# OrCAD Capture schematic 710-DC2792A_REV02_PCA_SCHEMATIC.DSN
size Custom; note: DUAL MASTER isoSPI ADAPTER
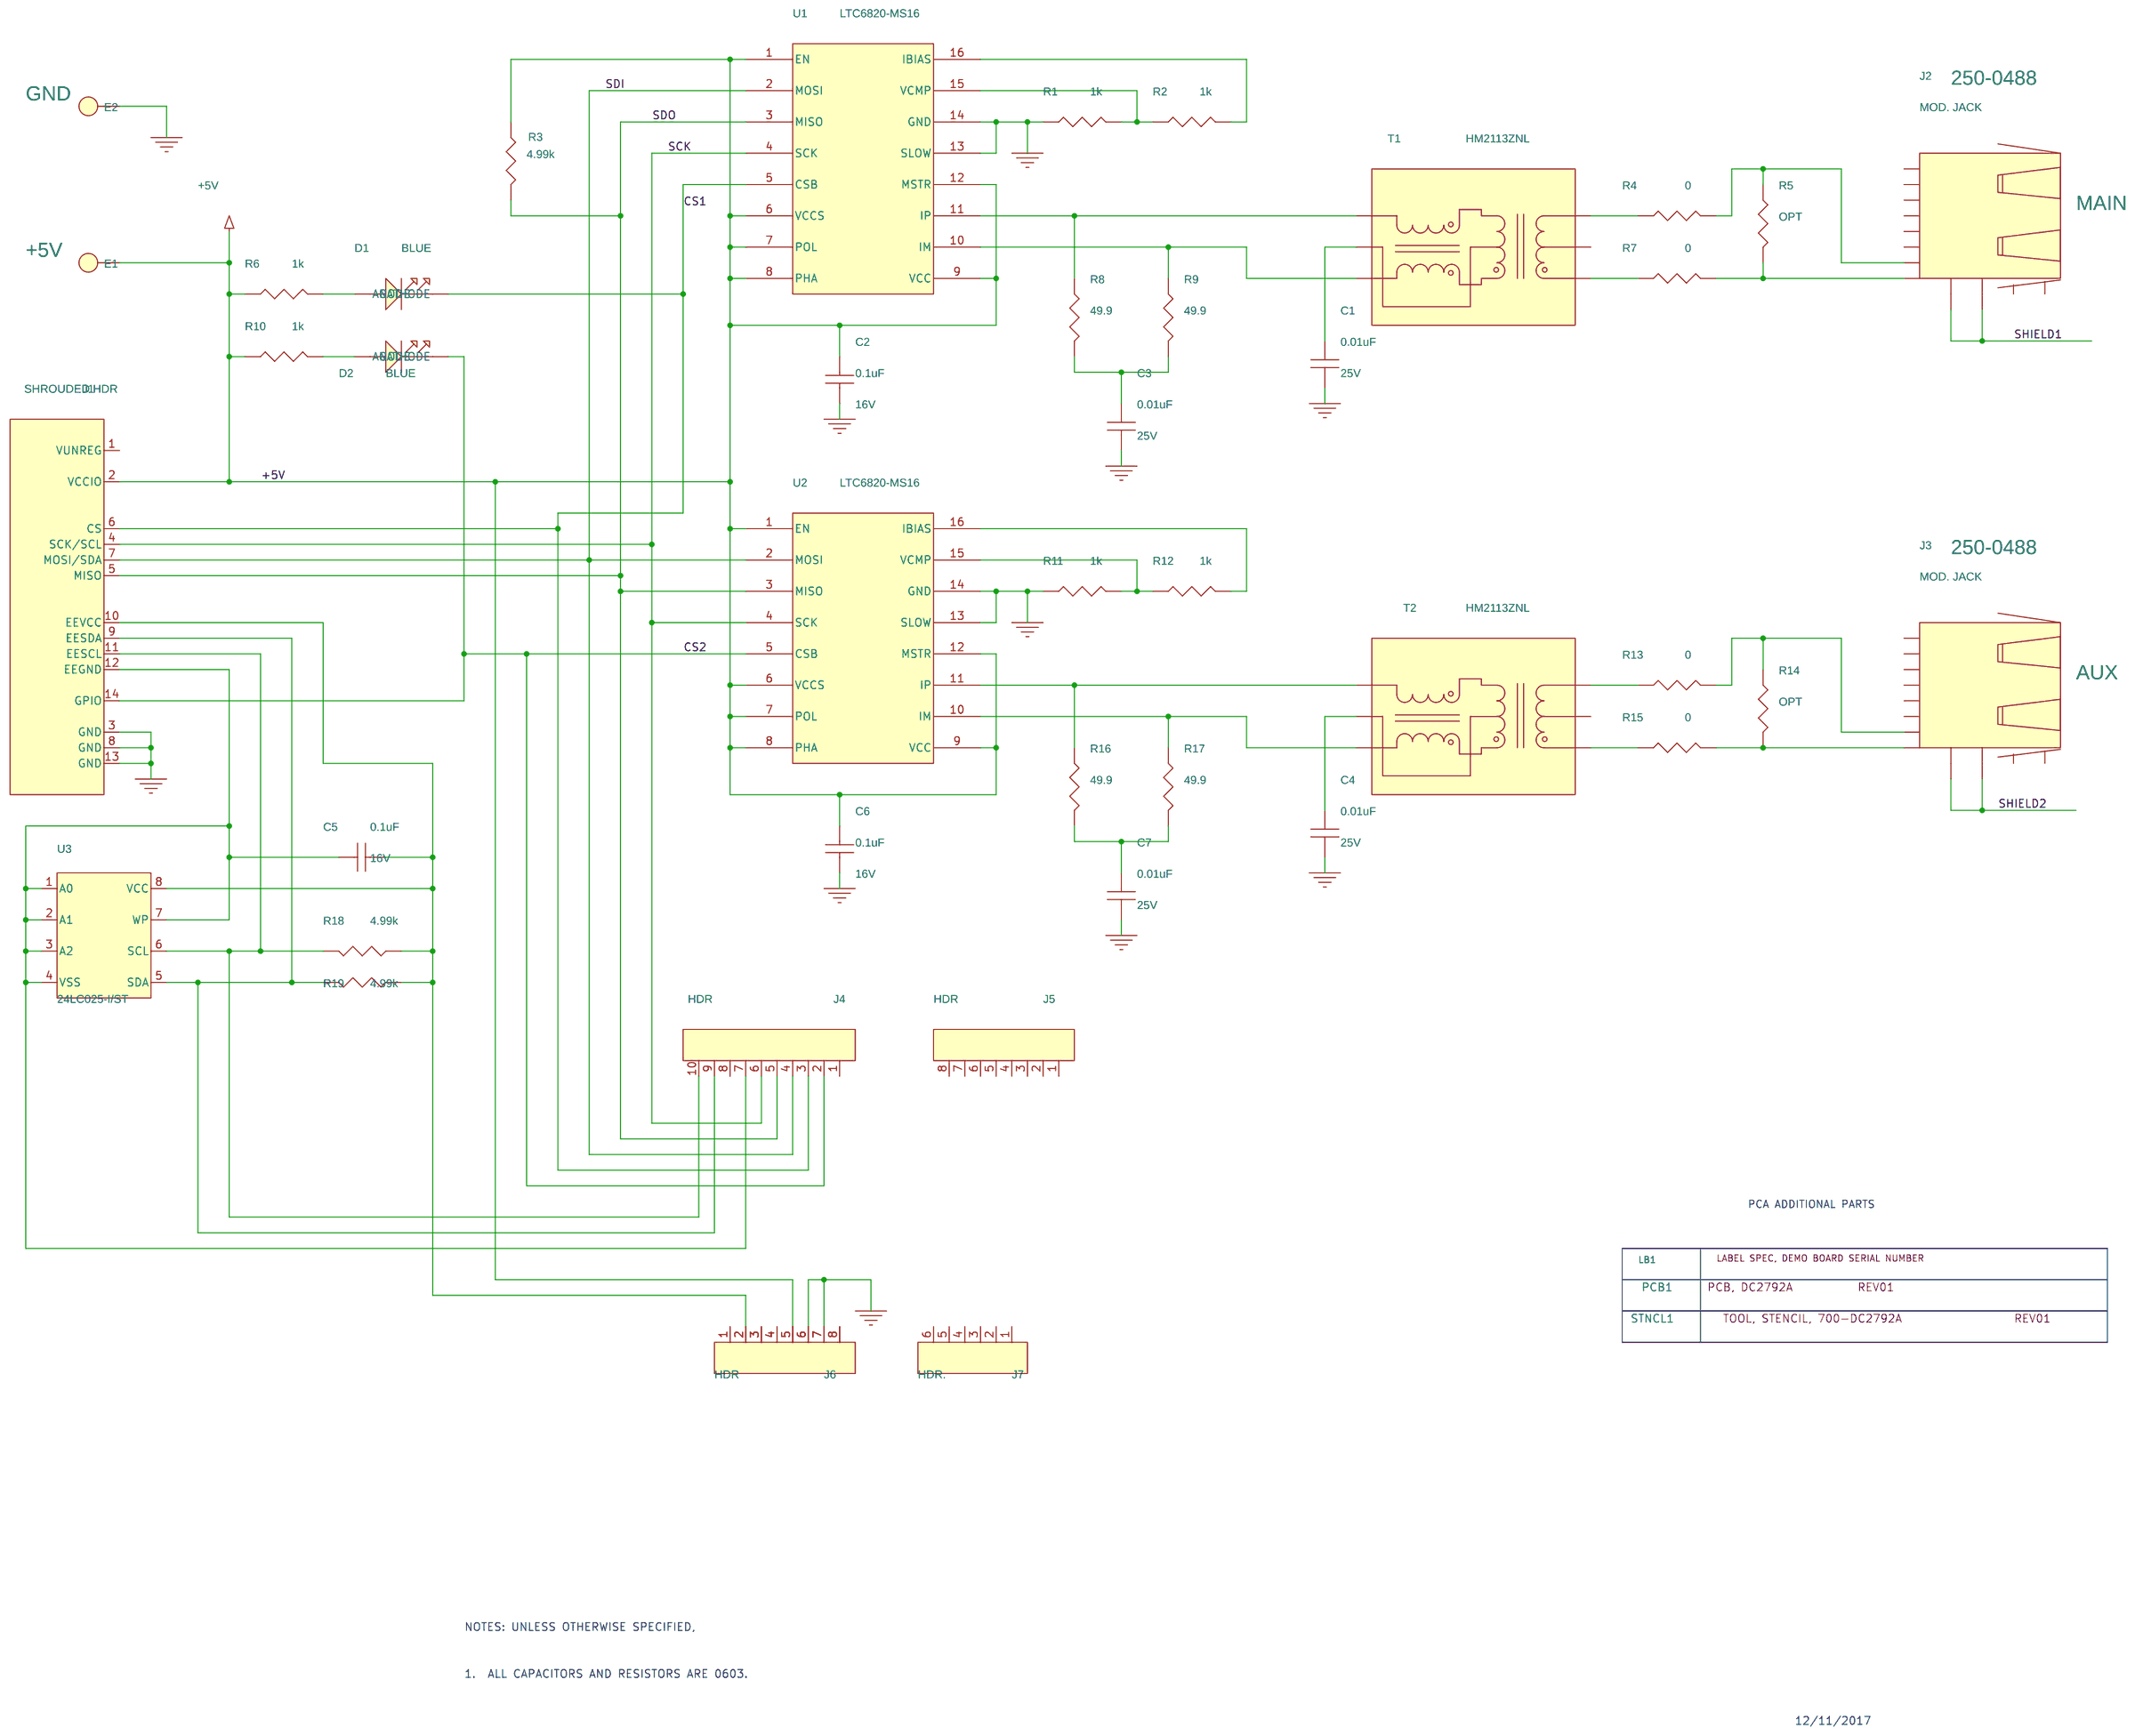
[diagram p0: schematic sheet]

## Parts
C1  0.01uF  [CC0603N]
C2  0.1uF  [CC0603N]
C3  0.01uF  [CC0603N]
C4  0.01uF  [CC0603N]
C5  0.1uF  [CC0603N]
C6  0.1uF  [CC0603N]
C7  0.01uF  [CC0603N]
D1  BLUE  [LED_0603]
D2  BLUE  [LED_0603]
E1  TEST POINT  [MILLMAX2308]
E2  TEST POINT  [MILLMAX2308]
J1  SHROUDED HDR  [HD2X7-079-MOLEX]
J2  MOD. JACK  [CON-RJ45-5406298]
J3  MOD. JACK  [CON-RJ45-5406298]
J4  HDR  [HD1X10-100]
J5  HDR  [HD1X8-100]
J6  HDR  [HD1X8-100]
J7  HDR.  [HD1X6-100]
LB1  LABEL  [895-0154_REV01]
PCB1  PCB, DC2792A
R1  1k  [CR0603N]
R2  1k  [CR0603N]
R3  4.99k  [CR0603N]
R4  0  [CR0603N]
R5  OPT  [CR0603N]
R6  1k  [CR0603N]
R7  0  [CR0603N]
R8  49.9  [CR0603N]
R9  49.9  [CR0603N]
R10  1k  [CR0603N]
R11  1k  [CR0603N]
R12  1k  [CR0603N]
R13  0  [CR0603N]
R14  OPT  [CR0603N]
R15  0  [CR0603N]
R16  49.9  [CR0603N]
R17  49.9  [CR0603N]
R18  4.99k  [CR0603N]
R19  4.99k  [CR0603N]
STNCL1  TOOL, STENCIL, DC2792A
T1  HM2113ZNL  [PULSE-HM2113ZNL]
T2  HM2113ZNL  [PULSE-HM2113ZNL]
U1  LTC6820-MS16  [LTC-MS-16-1669]
U2  LTC6820-MS16  [LTC-MS-16-1669]
U3  24LC025-I/ST  [MICROCHIP-TSSOP-8]

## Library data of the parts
C1 C3 C4 C7 = CAP: CAP.,0.01uF,X7R,25V,10%,0603; CLASS: DISCRETE; Dielectric Type: X7R; FPLIST: CC0603N,CC0603L,CC0603M; Inventory Qty: 19588; Manufacturer: AVX; Manufacturer PN: 06033C103KAT2A; PART_NUMBER: 150-3225; Package Size: 0603; Rated Voltage: 25V; Tolerance: 10%; UserField01: AEC-Q200, NO SUBS ALLOWED
C2 C5 C6 = CAP: CAP.,0.1uF,X7R,16V,10%,0603,AEC-Q200; CLASS: DISCRETE; Dielectric Type: X7R; FPLIST: CC0603N,CC0603L,CC0603M; Inventory Qty: 12770; Manufacturer: KEMET; Manufacturer PN: C0603C104K4RACAUTO; PART_NUMBER: 150-3311; Package Size: 0603; Rated Voltage: 16V; Tolerance: 10%; UserField01: AEC-Q200
D1 D2 = LED: LED,BLUE,WATER CLEAR,0603; CLASS: DISCRETE; Inventory Qty: 12068; Manufacturer: LUMEX; Manufacturer PN: SML-LXFP0603USBCTR; PART_NUMBER: 270-0119; Package Size: 0603 (1608 Metric); Package Type: 0603
E1 = TEST_POINT_.156_MILL-MAX_2308: TEST POINT,TURRET,0.064" MTG. HOLE,PCB 0.062" THICK; 1: +5V; BOM NOTES: NO STUFF; CLASS: IO; Inventory Qty: 835987; Manufacturer: MILL-MAX; Manufacturer PN: 2308-2-00-80-00-00-07-0; PART_NUMBER: 260-0004
E2 = TEST_POINT_.156_MILL-MAX_2308: TEST POINT,TURRET,0.064" MTG. HOLE,PCB 0.062" THICK; 1: GND; BOM NOTES: NO STUFF; CLASS: IO; Inventory Qty: 835987; Manufacturer: MILL-MAX; Manufacturer PN: 2308-2-00-80-00-00-07-0; PART_NUMBER: 260-0004
J1 = CONN_2X7_.079_MOLEX_RIBBON_A: CONN.,SHROUDED HDR,MALE,2x7,2mm,VERT,STR,THT; CLASS: IO; Inventory Qty: 26574; Manufacturer: MOLEX; Manufacturer PN: 87831-1420; PART_NUMBER: 250-0403
J2 = JACK_RJ45_SHIELDED: CONN.,MOD. JACK,FEMALE,8POS, 1PORT,R/A THT,SHIELDED; 1: MAIN; CLASS: IO; Inventory Qty: 9320; Manufacturer: TE CONNECTIVITY; Manufacturer PN: 5406298-1; PART_NUMBER: 250-0488
J3 = JACK_RJ45_SHIELDED: CONN.,MOD. JACK,FEMALE,8POS, 1PORT,R/A THT,SHIELDED; 1: AUX; CLASS: IO; Inventory Qty: 9320; Manufacturer: TE CONNECTIVITY; Manufacturer PN: 5406298-1; PART_NUMBER: 250-0488
J4 = CON10_0: CONN.,HDR,MALE,1x10,2.54mm,VERT, STR, THT; CLASS: IO; Inventory Qty: 11032; Manufacturer: SAMTEC; Manufacturer PN: TSW-110-07-L-S; PART_NUMBER: 250-0606
J5 J6 = CON8: CONN.,HDR,MALE,1x8,2.54mm,VERT, STR, THT; CLASS: IO; Inventory Qty: 4158; Manufacturer: SAMTEC; Manufacturer PN: TSW-108-07-L-S; PART_NUMBER: 250-0573
J7 = CON6: CONN.,HDR.,MALE,1x6,2.54mm,THT, STR; CLASS: IO; Inventory Qty: 12302; Manufacturer: SAMTEC; Manufacturer PN: TSW-106-07-L-S; PART_NUMBER: 250-0537
LB1 = BLANK_LABEL: LABEL SPEC, DEMO BOARD SERIAL NUMBER; Inventory Qty: 0; Manufacturer: BRADY; Manufacturer PN: THT-96-717-10; PART_NUMBER: 895-0154
PCB1 = BLANK_PCB_PART: BOM Notes: REV01; CLASS: DISCRETE; Inventory Qty: 0; Manufacturer: EAGLE TECH. INC.; Manufacturer PN: 600-DC2792A; PART_NUMBER: 600-DC2792A
R1 R2 R6 R10-R12 = RES: RES.,1k OHMS,5%,1/10W,0603; CLASS: DISCRETE; FPLIST: CR0603N,CR0603L,CR0603M; Inventory Qty: 35510; Manufacturer: SAMSUNG; Manufacturer PN: RC1608J102CS; PART_NUMBER: 100-0020; Package Size: 0603; Rated Power: 1/10W; Temperature Coefficient: 100ppm/C; Tolerance: 5%
R3 R18 R19 = RES: RES.,4.99k OHMS,1%,1/10W,0603; CLASS: DISCRETE; FPLIST: CR0603N,CR0603L,CR0603M; Inventory Qty: 62059; Manufacturer: PANASONIC; Manufacturer PN: ERJ3EKF4991V; PART_NUMBER: 100-0121; Package Size: 0603; Rated Power: 1/10W; Temperature Coefficient: 100ppm/C; Tolerance: 1%
R4 R7 R13 R15 = RES: RES.,0 OHM,1/10W,0603,AEC-Q200; CLASS: DISCRETE; FPLIST: CR0603N,CR0603L,CR0603M; Inventory Qty: 627023; Manufacturer: VISHAY; Manufacturer PN: CRCW06030000Z0EA; PART_NUMBER: 100-0009; Package Size: 0603; Rated Power: 1/10W
R5 R14 = RES: RES., OPTION, 0603; CLASS: DISCRETE; FPLIST: CR0603N,CR0603L,CR0603M; PART_NUMBER: 100-2374; Package Size: 0603
R8 R9 R16 R17 = RES: RES.,49.9 OHMS,1%,1/10W,0603; CLASS: DISCRETE; FPLIST: CR0603N,CR0603L,CR0603M; Inventory Qty: 58114; Manufacturer: PANASONIC; Manufacturer PN: ERJ3EKF49R9V; PART_NUMBER: 100-0115; Package Size: 0603; Rated Power: 1/10W; Temperature Coefficient: +/-100ppm; Tolerance: 1%
STNCL1 = BLANK_STENCIL_PART: TOOL, STENCIL, 700-DC2792A; BOM Notes: REV01; CLASS: DISCRETE; Inventory Qty: 0; Manufacturer: LINEAR TECH.; Manufacturer PN: 830-DC2792A; PART_NUMBER: 830-DC2792A
T1 T2 = PULSE-HM2113ZNL: TRANSFORMER,CMC,SGL,1:1 +/-2%,4.3kV,6-pin SMT,AEC-Q200; CLASS: DISCRETE; Inventory Qty: 68; Manufacturer: PULSE; PART_NUMBER: 410-0100; Turns Ratio: 1:1 +/-2%
U1 U2 = LTC6820-MS-ALT1: IC,isoSPI Isolated Comm.Interface,16-pin MSOP; CLASS: IC; Inventory Qty: 69; Manufacturer: LINEAR TECH.; Manufacturer PN: LTC6820IMS#PBF; PART_NUMBER: LTC6820IMS#PBF; Package Size: MS16; Package Type: 16-pin MSOP; Supply Voltage: 2.7V-5.5 V
U3 = 24LC025-I_ST_TSSOP-8: IC, MEMORY,EEPROM,2Kb (256x8),TSSOP-8,400kHz; CLASS: IC; Inventory Qty: 11792; Manufacturer: Microchip; PART_NUMBER: 380-0087; Package Size: TSSOP-8; Package Type: TSSOP-8

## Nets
+5V: C2.1 C6.1 E1.1(A) J1.2(VCCIO) J6.5 R3.1 R6.1 R10.1 U1.1(EN) U1.6(VCCS) U1.7(POL) U1.8(PHA) U1.9(VCC) U1.12(MSTR) U2.1(EN) U2.6(VCCS) U2.7(POL) U2.8(PHA) U2.9(VCC) U2.12(MSTR)
GND: C1.2 C2.2 C3.2 C4.2 C6.2 C7.2 E2.1(A) J1.3(GND) J1.8(GND) J1.13(GND) J6.6 J6.7 R1.1 R11.1 U1.13(SLOW) U1.14(GND) U2.13(SLOW) U2.14(GND)
CS1: D1.1(CATHODE) J1.6(CS) J4.3 U1.5(CSB)
CS2: D2.1(CATHODE) J1.14(GPIO) J4.2 U2.5(CSB)
SCK: J1.4(SCK/SCL) J4.6 U1.4(SCK) U2.4(SCK)
SDI: J1.7(MOSI/SDA) J4.4 U1.2(MOSI) U2.2(MOSI)
SDO: J1.5(MISO) J4.5 R3.2 U1.3(MISO) U2.3(MISO)
SHIELD1: J2.S1 J2.S2
SHIELD2: J3.S1 J3.S2
N27407114: C5.1 J1.12(EEGND) J4.7 U3.1(A0) U3.2(A1) U3.3(A2) U3.4(VSS) U3.7(WP)
N27407193: J1.11(EESCL) J4.10 R18.1 U3.6(SCL)
N27407213: J1.9(EESDA) J4.9 R19.1 U3.5(SDA)
N27407390: C5.2 J1.10(EEVCC) J6.2 R18.2 R19.2 U3.8(VCC)
N27408489: R1.2 R2.1 U1.15(VCMP)
N27408492: R2.2 U1.16(IBIAS)
N27408890: R8.1 T1.4 U1.11(IP)
N27408904: R9.1 T1.6 U1.10(IM)
N27408920: C1.1 T1.5
N27409119: C3.1 R8.2 R9.2
N27409499: J2.2 R4.2 R5.1
N27409511: J2.1 R5.2 R7.2
N27409863: R11.2 R12.1 U2.15(VCMP)
N27409865: R12.2 U2.16(IBIAS)
N27409893: R16.1 T2.4 U2.11(IP)
N27409895: R17.1 T2.6 U2.10(IM)
N27409901: C4.1 T2.5
N27409942: C7.1 R16.2 R17.2
N27409983: J3.2 R13.2 R14.1
N27409997: J3.1 R14.2 R15.2
N27411834: D1.2(ANODE) R6.2
N27411837: D2.2(ANODE) R10.2
N27422700: R7.1 T1.1
N27422702: R4.1 T1.3
N27422768: R15.1 T2.1
N27422770: R13.1 T2.3

Not connected (* = marked no-connect by the designer): J1 1(VUNREG); J2 3 4 5 6 7 8; J3 3 4 5 6 7 8; J4 1 8; J5 1 2 3 4 5 6 7 8; J6 1 3 4 8; J7 1 2 3 4 5 6; T1 2; T2 2

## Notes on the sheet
- PCA ADDITIONAL PARTS
- NOTES: UNLESS OTHERWISE SPECIFIED,
- 1.  ALL CAPACITORS AND RESISTORS ARE 0603.
- 12/11/2017
